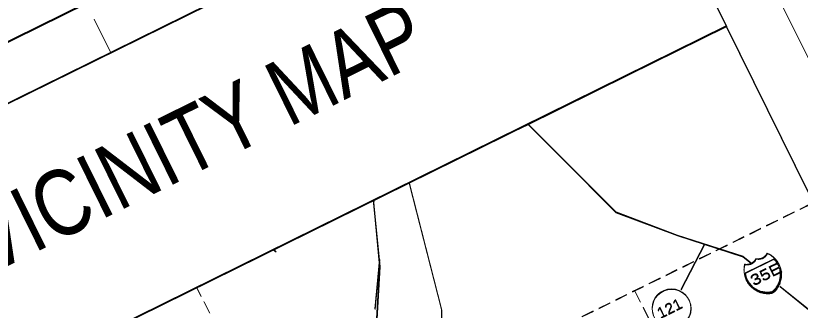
# Model space of a CAD drawing. Extents: x 2356606 to 2371222, y 6973096 to 6982644.
# Drawn here: x 2357059.9 to 2357437.7, y 6973867.4 to 6974009.4 of the extents above; entities that cross this region are included whole.
import ezdxf

# ---------------------------------------------------------------- set-up
doc = ezdxf.new("R2010")
doc.units = 0
doc.header["$LTSCALE"] = 2
doc.linetypes.add('MEDIUM_DASHED', pattern=[4.5, 3, -1.5])
doc.layers.add('62', color=7, linetype='Continuous', lineweight=13)
doc.layers.add('63', color=7, linetype='Continuous', lineweight=13)

msp = doc.modelspace()

# ---------------------------------------------------------------- linework, layer by layer
at = {"layer": '62'}
for p, q in [((2357278.212, 6974319.925), (2357633.685, 6973599.663)), ((2357097.709, 6974007.8), (2357105.729, 6973991.55)), ((2357305.337, 6973956.214), (2357372.248, 6973989.237)), ((2357183.966, 6973896.563), (2357185.288, 6973895.461)), ((2357380.319, 6973877.139), (2357391.756, 6973899.219)), ((2357233.036, 6973867.86), (2357235.256, 6973891.891))]:
    msp.add_line(p, q, dxfattribs=at)
at = {"layer": '62', "lineweight": 25}
msp.add_line((2356999.05, 6973805.301), (2357402.214, 6974004.278), dxfattribs=at)
at = {"layer": '62', "linetype": 'MEDIUM_DASHED'}
for p, q in [((2357443, 6973918.637), (2357041.025, 6973720.25)), ((2357189.922, 6973793.734), (2357147.06, 6973878.349)), ((2357358.049, 6973876.711), (2357485.75, 6973626.399))]:
    msp.add_line(p, q, dxfattribs=at)
at = {"layer": '62', "lineweight": 40}
msp.add_lwpolyline([(2357000.317, 6974057.993), (2357035.475, 6973986.756), (2357293.714, 6974114.204)], dxfattribs=at)
at = {"layer": '62', "lineweight": 25}
for points in [[(2356999.05, 6973805.301), (2356946.031, 6973912.733), (2357348.892, 6974111.56), (2357402.214, 6974004.278)], [(2356999.05, 6973805.301), (2357204.965, 6973388.075), (2357608.13, 6973587.05), (2357402.214, 6974004.278)], [(2357306.592, 6973957.083), (2357322.708, 6973940.898), (2357348.978, 6973914.567), (2357378.626, 6973903.454), (2357410.203, 6973893.266), (2357414.151, 6973890.098)], [(2357232.433, 6973920.486), (2357232.285, 6973919.105), (2357235.277, 6973888.336), (2357233.475, 6973857.563), (2357231.613, 6973836.018), (2357235.461, 6973803.512)], [(2357428.062, 6973878.845), (2357445.085, 6973865.09), (2357468.122, 6973836.159), (2357493.515, 6973819.284)]]:
    msp.add_lwpolyline(points, dxfattribs=at)
at = {"layer": '62'}
for points in [[(2357265.199, 6973805.693), (2357265.056, 6973867.503), (2357249.594, 6973928.478)], [(2357417.382, 6973891.994), (2357417.591, 6973891.972), (2357417.814, 6973891.982), (2357417.985, 6973891.991), (2357418.206, 6973891.999), (2357418.398, 6973892.067), (2357418.599, 6973892.066), (2357418.77, 6973892.127), (2357418.972, 6973892.174), (2357419.154, 6973892.216), (2357419.346, 6973892.284), (2357419.507, 6973892.365), (2357419.689, 6973892.453), (2357419.848, 6973892.532), (2357420.011, 6973892.613), (2357420.202, 6973892.733), (2357420.323, 6973892.843), (2357420.465, 6973892.964), (2357420.636, 6973893.074), (2357420.78, 6973893.243), (2357420.931, 6973893.344), (2357421.072, 6973893.514), (2357421.206, 6973893.654), (2357421.325, 6973893.815), (2357421.437, 6973893.995), (2357421.56, 6973894.156), (2357421.69, 6973894.344), (2357421.821, 6973894.535), (2357421.923, 6973894.737), (2357422.294, 6973894.594), (2357422.664, 6973894.4), (2357423.049, 6973894.186), (2357423.449, 6973893.935), (2357423.829, 6973893.671), (2357424.22, 6973893.386), (2357424.602, 6973893.072), (2357424.984, 6973892.759), (2357425.373, 6973892.374), (2357425.726, 6973892.02), (2357426.073, 6973891.615), (2357426.403, 6973891.203), (2357426.713, 6973890.778), (2357427.023, 6973890.354), (2357427.263, 6973889.918), (2357427.53, 6973889.475), (2357427.738, 6973888.951), (2357427.98, 6973888.416), (2357428.138, 6973887.892), (2357428.318, 6973887.378), (2357428.475, 6973886.852), (2357428.552, 6973886.288), (2357428.63, 6973885.774), (2357428.698, 6973885.23), (2357428.714, 6973884.687), (2357428.711, 6973884.133), (2357428.67, 6973883.61), (2357428.626, 6973883.088), (2357428.533, 6973882.514), (2357428.42, 6973881.982), (2357428.277, 6973881.46), (2357428.103, 6973880.895), (2357427.97, 6973880.505), (2357427.826, 6973880.082), (2357427.622, 6973879.682), (2357427.439, 6973879.29), (2357427.218, 6973878.879), (2357426.985, 6973878.487), (2357426.76, 6973878.125), (2357426.536, 6973877.766), (2357426.293, 6973877.445), (2357426.05, 6973877.124), (2357425.797, 6973876.823), (2357425.532, 6973876.541), (2357425.28, 6973876.343), (2357425.039, 6973876.122), (2357424.777, 6973875.943), (2357424.533, 6973875.823)], [(2357424.533, 6973875.823), (2357424.372, 6973875.743), (2357424.232, 6973875.673), (2357424.051, 6973875.634), (2357423.899, 6973875.584), (2357423.718, 6973875.545), (2357423.536, 6973875.507), (2357423.306, 6973875.467), (2357423.094, 6973875.439), (2357422.891, 6973875.44), (2357422.67, 6973875.431), (2357422.428, 6973875.411), (2357422.207, 6973875.402), (2357421.964, 6973875.384), (2357421.755, 6973875.404), (2357421.494, 6973875.427), (2357421.242, 6973875.428), (2357420.999, 6973875.459), (2357420.728, 6973875.502), (2357420.488, 6973875.533), (2357420.245, 6973875.562), (2357419.994, 6973875.616), (2357419.731, 6973875.687), (2357419.492, 6973875.719), (2357419.26, 6973875.779), (2357419.008, 6973875.832), (2357418.778, 6973875.893), (2357418.537, 6973875.975), (2357418.315, 6973876.066), (2357418.064, 6973876.118), (2357417.853, 6973876.188), (2357417.652, 6973876.29), (2357417.422, 6973876.404), (2357417.021, 6973876.605), (2357416.577, 6973876.84), (2357416.168, 6973877.114), (2357415.776, 6973877.348), (2357415.364, 6973877.621), (2357414.975, 6973877.904), (2357414.602, 6973878.199), (2357414.251, 6973878.552), (2357413.893, 6973878.875), (2357413.562, 6973879.24), (2357413.251, 6973879.616), (2357412.942, 6973879.99), (2357412.62, 6973880.384), (2357412.362, 6973880.808), (2357412.081, 6973881.273), (2357411.833, 6973881.726), (2357411.645, 6973882.211), (2357411.465, 6973882.675), (2357411.297, 6973883.17), (2357411.148, 6973883.674), (2357411.02, 6973884.186), (2357410.913, 6973884.711), (2357410.844, 6973885.203), (2357410.758, 6973885.738), (2357410.76, 6973886.241), (2357410.744, 6973886.735), (2357410.754, 6973887.215), (2357410.777, 6973887.68), (2357410.84, 6973888.163), (2357410.861, 6973888.575), (2357410.955, 6973888.996), (2357411.067, 6973889.379), (2357411.29, 6973889.338), (2357411.52, 6973889.325), (2357411.752, 6973889.316), (2357411.953, 6973889.315), (2357412.184, 6973889.302), (2357412.385, 6973889.302), (2357412.596, 6973889.331), (2357412.797, 6973889.33), (2357412.968, 6973889.39), (2357413.17, 6973889.389), (2357413.363, 6973889.457), (2357413.547, 6973889.497), (2357413.767, 6973889.557), (2357413.917, 6973889.606), (2357414.078, 6973889.685), (2357414.281, 6973889.785), (2357414.442, 6973889.865), (2357414.604, 6973889.945), (2357414.776, 6973890.056), (2357414.916, 6973890.175), (2357415.056, 6973890.293), (2357415.209, 6973890.395), (2357415.372, 6973890.576), (2357415.523, 6973890.675), (2357415.646, 6973890.834), (2357415.776, 6973890.976), (2357415.92, 6973891.145), (2357416.049, 6973891.336), (2357416.171, 6973891.497), (2357416.284, 6973891.678), (2357416.394, 6973891.858), (2357416.515, 6973892.068), (2357416.737, 6973892.027), (2357416.95, 6973892.006), (2357417.18, 6973891.995), (2357417.382, 6973891.994)]]:
    msp.add_lwpolyline(points, dxfattribs=at)
msp.add_lwpolyline([(2357425.039, 6973891.984), (2357411.376, 6973885.241), (2357411.397, 6973885.001), (2357411.436, 6973884.717), (2357411.494, 6973884.396), (2357411.603, 6973883.972), (2357411.702, 6973883.519), (2357411.84, 6973883.036), (2357412.047, 6973882.513), (2357412.318, 6973881.967), (2357412.593, 6973881.401), (2357412.915, 6973880.857), (2357413.276, 6973880.33), (2357413.664, 6973879.845), (2357414.066, 6973879.388), (2357414.477, 6973878.963), (2357414.916, 6973878.529), (2357415.399, 6973878.164), (2357415.878, 6973877.8), (2357416.369, 6973877.465), (2357416.911, 6973877.18), (2357417.453, 6973876.896), (2357418.045, 6973876.662), (2357418.649, 6973876.457), (2357419.234, 6973876.292), (2357419.855, 6973876.149), (2357420.148, 6973876.067), (2357420.461, 6973876.047), (2357420.762, 6973875.994), (2357421.093, 6973875.983), (2357421.385, 6973875.951), (2357421.708, 6973875.907), (2357422.009, 6973875.907), (2357422.311, 6973875.906), (2357422.602, 6973875.925), (2357422.875, 6973875.933), (2357423.166, 6973875.95), (2357423.399, 6973875.992), (2357423.669, 6973876.05), (2357423.891, 6973876.107), (2357424.113, 6973876.167), (2357424.324, 6973876.247), (2357424.585, 6973876.426), (2357424.9, 6973876.655), (2357425.173, 6973876.917), (2357425.468, 6973877.237), (2357425.751, 6973877.527), (2357426.012, 6973877.909), (2357426.258, 6973878.28), (2357426.522, 6973878.662), (2357426.765, 6973879.081), (2357426.98, 6973879.515), (2357427.181, 6973879.915), (2357427.355, 6973880.326), (2357427.537, 6973880.718), (2357427.671, 6973881.11), (2357427.793, 6973881.472), (2357427.836, 6973881.793), (2357427.959, 6973882.357), (2357428.022, 6973882.89), (2357428.087, 6973883.422), (2357428.117, 6973883.966), (2357428.151, 6973884.459), (2357428.133, 6973884.952), (2357428.105, 6973885.413), (2357428.048, 6973885.888), (2357427.991, 6973886.36), (2357427.932, 6973886.785), (2357427.812, 6973887.228), (2357427.684, 6973887.641), (2357427.555, 6973888.056), (2357427.405, 6973888.459), (2357427.236, 6973888.852), (2357427.048, 6973889.237), (2357426.779, 6973889.782), (2357426.49, 6973890.264), (2357426.187, 6973890.669), (2357425.929, 6973891.043), (2357425.639, 6973891.379), (2357425.4, 6973891.609), (2357425.2, 6973891.811)], close=True, dxfattribs=at)
msp.add_circle((2357375.818, 6973868.156), 9.364, dxfattribs=at)
at = {"layer": '63'}
for p, q in [((2357097.709, 6974007.8), (2357105.729, 6973991.55)), ((2357305.207, 6973956.477), (2357372.118, 6973989.5)), ((2357183.836, 6973896.826), (2357185.158, 6973895.724)), ((2357380.189, 6973877.402), (2357391.626, 6973899.482)), ((2357232.906, 6973868.123), (2357235.126, 6973892.154))]:
    msp.add_line(p, q, dxfattribs=at)
at = {"layer": '63', "lineweight": 25}
msp.add_line((2356998.92, 6973805.564), (2357402.084, 6974004.541), dxfattribs=at)
at = {"layer": '63', "linetype": 'MEDIUM_DASHED'}
for p, q in [((2357442.87, 6973918.9), (2357040.895, 6973720.513)), ((2357189.792, 6973793.997), (2357146.93, 6973878.612)), ((2357357.919, 6973876.974), (2357485.62, 6973626.662))]:
    msp.add_line(p, q, dxfattribs=at)
at = {"layer": '63', "lineweight": 25}
for points in [[(2356998.92, 6973805.564), (2356945.901, 6973912.996), (2357348.762, 6974111.823), (2357402.084, 6974004.541)], [(2356998.92, 6973805.564), (2357204.835, 6973388.338), (2357608, 6973587.313), (2357402.084, 6974004.541)], [(2357306.462, 6973957.346), (2357322.578, 6973941.161), (2357348.848, 6973914.83), (2357378.496, 6973903.717), (2357410.073, 6973893.529), (2357414.021, 6973890.361)], [(2357232.303, 6973920.749), (2357232.155, 6973919.368), (2357235.147, 6973888.599), (2357233.345, 6973857.826), (2357231.483, 6973836.281), (2357235.331, 6973803.775)], [(2357427.932, 6973879.108), (2357444.955, 6973865.353), (2357467.992, 6973836.422), (2357493.385, 6973819.547)]]:
    msp.add_lwpolyline(points, dxfattribs=at)
at = {"layer": '63', "lineweight": 40}
msp.add_lwpolyline([(2357000.317, 6974057.993), (2357035.475, 6973986.756), (2357293.714, 6974114.204)], dxfattribs=at)
at = {"layer": '63'}
for points in [[(2357265.069, 6973805.956), (2357264.926, 6973867.766), (2357249.464, 6973928.741)], [(2357417.252, 6973892.257), (2357417.461, 6973892.235), (2357417.684, 6973892.245), (2357417.855, 6973892.254), (2357418.076, 6973892.262), (2357418.268, 6973892.33), (2357418.469, 6973892.329), (2357418.64, 6973892.39), (2357418.842, 6973892.437), (2357419.024, 6973892.479), (2357419.216, 6973892.547), (2357419.377, 6973892.628), (2357419.559, 6973892.716), (2357419.718, 6973892.795), (2357419.881, 6973892.876), (2357420.072, 6973892.996), (2357420.193, 6973893.106), (2357420.335, 6973893.227), (2357420.506, 6973893.337), (2357420.65, 6973893.506), (2357420.801, 6973893.607), (2357420.942, 6973893.777), (2357421.076, 6973893.917), (2357421.195, 6973894.078), (2357421.307, 6973894.258), (2357421.43, 6973894.419), (2357421.56, 6973894.607), (2357421.691, 6973894.798), (2357421.793, 6973895), (2357422.164, 6973894.857), (2357422.534, 6973894.663), (2357422.919, 6973894.449), (2357423.319, 6973894.198), (2357423.699, 6973893.934), (2357424.09, 6973893.649), (2357424.472, 6973893.335), (2357424.854, 6973893.022), (2357425.243, 6973892.637), (2357425.596, 6973892.283), (2357425.943, 6973891.878), (2357426.273, 6973891.466), (2357426.583, 6973891.041), (2357426.893, 6973890.617), (2357427.133, 6973890.181), (2357427.4, 6973889.738), (2357427.608, 6973889.214), (2357427.85, 6973888.679), (2357428.008, 6973888.155), (2357428.188, 6973887.641), (2357428.345, 6973887.115), (2357428.422, 6973886.551), (2357428.5, 6973886.037), (2357428.568, 6973885.493), (2357428.584, 6973884.95), (2357428.581, 6973884.396), (2357428.54, 6973883.873), (2357428.496, 6973883.351), (2357428.403, 6973882.777), (2357428.29, 6973882.245), (2357428.147, 6973881.723), (2357427.973, 6973881.158), (2357427.84, 6973880.768), (2357427.696, 6973880.345), (2357427.492, 6973879.945), (2357427.309, 6973879.553), (2357427.088, 6973879.142), (2357426.855, 6973878.75), (2357426.63, 6973878.388), (2357426.406, 6973878.029), (2357426.163, 6973877.708), (2357425.92, 6973877.387), (2357425.667, 6973877.086), (2357425.402, 6973876.804), (2357425.15, 6973876.606), (2357424.909, 6973876.385), (2357424.647, 6973876.206), (2357424.403, 6973876.086)], [(2357424.403, 6973876.086), (2357424.242, 6973876.006), (2357424.102, 6973875.936), (2357423.921, 6973875.897), (2357423.769, 6973875.847), (2357423.588, 6973875.808), (2357423.406, 6973875.77), (2357423.176, 6973875.73), (2357422.964, 6973875.702), (2357422.761, 6973875.703), (2357422.54, 6973875.694), (2357422.298, 6973875.674), (2357422.077, 6973875.665), (2357421.834, 6973875.647), (2357421.625, 6973875.667), (2357421.364, 6973875.69), (2357421.112, 6973875.691), (2357420.869, 6973875.722), (2357420.598, 6973875.765), (2357420.358, 6973875.796), (2357420.115, 6973875.825), (2357419.864, 6973875.879), (2357419.601, 6973875.95), (2357419.362, 6973875.982), (2357419.13, 6973876.042), (2357418.878, 6973876.095), (2357418.648, 6973876.156), (2357418.407, 6973876.238), (2357418.185, 6973876.329), (2357417.934, 6973876.381), (2357417.723, 6973876.451), (2357417.522, 6973876.553), (2357417.292, 6973876.667), (2357416.891, 6973876.868), (2357416.447, 6973877.103), (2357416.038, 6973877.377), (2357415.646, 6973877.611), (2357415.234, 6973877.884), (2357414.845, 6973878.167), (2357414.472, 6973878.462), (2357414.121, 6973878.815), (2357413.763, 6973879.138), (2357413.432, 6973879.503), (2357413.121, 6973879.879), (2357412.812, 6973880.253), (2357412.49, 6973880.647), (2357412.232, 6973881.071), (2357411.951, 6973881.536), (2357411.703, 6973881.989), (2357411.515, 6973882.474), (2357411.335, 6973882.938), (2357411.167, 6973883.433), (2357411.018, 6973883.937), (2357410.89, 6973884.449), (2357410.783, 6973884.974), (2357410.714, 6973885.466), (2357410.628, 6973886.001), (2357410.63, 6973886.504), (2357410.614, 6973886.998), (2357410.624, 6973887.478), (2357410.647, 6973887.943), (2357410.71, 6973888.426), (2357410.731, 6973888.838), (2357410.825, 6973889.259), (2357410.937, 6973889.642), (2357411.16, 6973889.601), (2357411.39, 6973889.588), (2357411.622, 6973889.579), (2357411.823, 6973889.578), (2357412.054, 6973889.565), (2357412.255, 6973889.565), (2357412.466, 6973889.594), (2357412.667, 6973889.593), (2357412.838, 6973889.653), (2357413.04, 6973889.652), (2357413.233, 6973889.72), (2357413.417, 6973889.76), (2357413.637, 6973889.82), (2357413.787, 6973889.869), (2357413.948, 6973889.948), (2357414.151, 6973890.048), (2357414.312, 6973890.128), (2357414.474, 6973890.208), (2357414.646, 6973890.319), (2357414.786, 6973890.438), (2357414.926, 6973890.556), (2357415.079, 6973890.658), (2357415.242, 6973890.839), (2357415.393, 6973890.938), (2357415.516, 6973891.097), (2357415.646, 6973891.239), (2357415.79, 6973891.408), (2357415.919, 6973891.599), (2357416.041, 6973891.76), (2357416.154, 6973891.941), (2357416.264, 6973892.121), (2357416.385, 6973892.331), (2357416.607, 6973892.29), (2357416.82, 6973892.269), (2357417.05, 6973892.258), (2357417.252, 6973892.257)]]:
    msp.add_lwpolyline(points, dxfattribs=at)
msp.add_lwpolyline([(2357424.909, 6973892.247), (2357411.246, 6973885.504), (2357411.267, 6973885.264), (2357411.306, 6973884.98), (2357411.364, 6973884.659), (2357411.473, 6973884.235), (2357411.572, 6973883.782), (2357411.71, 6973883.299), (2357411.917, 6973882.776), (2357412.188, 6973882.23), (2357412.463, 6973881.664), (2357412.785, 6973881.12), (2357413.146, 6973880.593), (2357413.534, 6973880.108), (2357413.936, 6973879.651), (2357414.347, 6973879.226), (2357414.786, 6973878.792), (2357415.269, 6973878.427), (2357415.748, 6973878.063), (2357416.239, 6973877.728), (2357416.781, 6973877.443), (2357417.323, 6973877.159), (2357417.915, 6973876.925), (2357418.519, 6973876.72), (2357419.104, 6973876.555), (2357419.725, 6973876.412), (2357420.018, 6973876.33), (2357420.331, 6973876.31), (2357420.632, 6973876.257), (2357420.963, 6973876.246), (2357421.255, 6973876.214), (2357421.578, 6973876.17), (2357421.879, 6973876.17), (2357422.181, 6973876.169), (2357422.472, 6973876.188), (2357422.745, 6973876.196), (2357423.036, 6973876.213), (2357423.269, 6973876.255), (2357423.539, 6973876.313), (2357423.761, 6973876.37), (2357423.983, 6973876.43), (2357424.194, 6973876.51), (2357424.455, 6973876.689), (2357424.77, 6973876.918), (2357425.043, 6973877.18), (2357425.338, 6973877.5), (2357425.621, 6973877.79), (2357425.882, 6973878.172), (2357426.128, 6973878.543), (2357426.392, 6973878.925), (2357426.635, 6973879.344), (2357426.85, 6973879.778), (2357427.051, 6973880.178), (2357427.225, 6973880.589), (2357427.407, 6973880.981), (2357427.541, 6973881.373), (2357427.663, 6973881.735), (2357427.706, 6973882.056), (2357427.829, 6973882.62), (2357427.892, 6973883.153), (2357427.957, 6973883.685), (2357427.987, 6973884.229), (2357428.021, 6973884.722), (2357428.003, 6973885.215), (2357427.975, 6973885.676), (2357427.918, 6973886.151), (2357427.861, 6973886.623), (2357427.802, 6973887.048), (2357427.682, 6973887.491), (2357427.554, 6973887.904), (2357427.425, 6973888.319), (2357427.275, 6973888.722), (2357427.106, 6973889.115), (2357426.918, 6973889.5), (2357426.649, 6973890.045), (2357426.36, 6973890.527), (2357426.057, 6973890.932), (2357425.799, 6973891.306), (2357425.509, 6973891.642), (2357425.27, 6973891.872), (2357425.07, 6973892.074)], close=True, dxfattribs=at)
msp.add_circle((2357375.688, 6973868.419), 9.364, dxfattribs=at)

# ---------------------------------------------------------------- texts
at = {"layer": '62'}
for s, height, width, p in [('VICINITY MAP', 31.45, 0.85, (2357047.141, 6973884.294)), ('35E', 5.099, 1.3, (2357415.311, 6973878.951)), ('121', 5.099, 1.1, (2357370.364, 6973863.145))]:
    msp.add_text(s, height=height, rotation=26.268, dxfattribs=dict(at, width=width)).set_placement(p)
at = {"layer": '63'}
for s, height, width, p in [('VICINITY MAP', 31.45, 0.85, (2357047.011, 6973884.558)), ('35E', 5.099, 1.3, (2357415.181, 6973879.215)), ('121', 5.099, 1.1, (2357370.234, 6973863.409))]:
    msp.add_text(s, height=height, rotation=26.268, dxfattribs=dict(at, width=width)).set_placement(p)

doc.saveas('drawing.dxf')
